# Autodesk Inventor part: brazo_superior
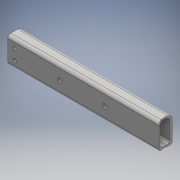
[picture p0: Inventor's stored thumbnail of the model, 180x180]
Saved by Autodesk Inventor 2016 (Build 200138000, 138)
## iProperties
Created: 2016-10
Part Number: brazo_superior
Material: Generic
Document SubType Name: Modeling
Designer: Ingenieria
Density: 1 g/cm^3
Appearance: Default
Mass: 948.547 g
Surface Area: 2981.55 cm^2
Volume: 948.547 cm^3
Author: Ingenieria
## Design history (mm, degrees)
sketch "Sketch1"
  geometry: C1 r 50.8 at (0, 0); C2 r 30.8 at (0, 0); 1 further point
  constraints: 2 centre point, 2 coincident
  dimensions: "d0" = 101.6 diameter of C1; "d1" = 61.6 diameter of C2
sketch "Sketch3"
  geometry: L1 (25, 38)-(25, -38); L2 (13, 50)-(-13, 50); L3 (-25, 38)-(-25, -38); L4 (-13, -50)-(13, -50); L5 (-19, -32)-(-19, 32); L6 (-7, 44)-(7, 44); L7 (19, 32)-(19, -32); L8 (7, -44)-(-7, -44); A1 r 12 centre (-7, 32) between (-7, 44) and (-19, 32); A2 r 12 centre (7, 32) between (19, 32) and (7, 44); A3 r 12 centre (-7, -32) between (-19, -32) and (-7, -44); A4 r 12 centre (7, -32) between (7, -44) and (19, -32); A5 r 12 centre (-13, 38) between (-13, 50) and (-25, 38); A6 r 12 centre (13, 38) between (25, 38) and (13, 50); A7 r 12 centre (13, -38) between (13, -50) and (25, -38); A8 r 12 centre (-13, -38) between (-25, -38) and (-13, -50); 5 further points
  constraints: 16 end point, 16 point on circle, 16 tangent, 8 centre point, 8 point on line, 4 perpendicular, 3 equal radius, 1 horizontal, 3 other
  dimensions: "d5" = 100 distance of point (25, 50) point (25, -50); "d6" = 50 distance of point (25, 50) point (-25, 50); "d7" = 100 distance of point (-25, 50) point (-25, -50); "d8" = 6 distance between parallel lines of L3 L5; "d9" = 12 radius of A1; "d10" = 12 radius of A5; "d11" = 12 radius of A6; "d12" = 12 radius of A7; "d13" = 12 radius of A8; "d14" = 25 distance from line of L1 point (0, 0); "d15" = 50 distance from line of point (0, 0) L4
extrude "Extrusion1" new body sketch "Sketch3" distance "d16" = 617; taper "d17" = 0 deg
extrude "Extrusion2" cut sketch "Sketch1" stored distance "d18" = 100; taper "d19" = 0 deg
sketch "Sketch4"
  geometry: L1 (567.892, -12)-(566.2, -12) reference; L2 (566.2, -6)-(566.685, -6) reference; L3 (0, 0)-(0, 76) reference; L4 (572.777, 0)-(572.777, 76) reference; L5 (566.2, -6)-(566.2, 175.196); L6 (0, 76)-(0, 0) reference; L7 (0, 38)-(566.2, 38); L8 (283.1, 38)-(283.1, 141.275); L9 (368.1, 38)-(368.1, 141.275); L10 (198.1, 38)-(198.1, 141.275); L11 (0, 58)-(574.2, 58); L12 (0, 18)-(574.2, 18); L13 (27, 0)-(27, 76); C1 r 8.5 at (198.1, 38); C2 r 8.5 at (368.1, 38); C3 r 6.5 at (27, 58); C4 r 6.5 at (27, 18); 1 further point
  constraints: 16 end point, 5 parallel, 5 point on line, 4 centre point, 2 coincident, 2 midpoint, 2 vertical, 1 perpendicular
  dimensions: "d22" = 85 distance between parallel lines of L8 L9; "d23" = 85 distance between parallel lines of L8 L10; "d24" = 17 diameter of C1; "d25" = 17 diameter of C2; "d26" = 20 distance between parallel lines of L7 L11; "d27" = 20 distance between parallel lines of L7 L12; "d28" = 27 distance between parallel lines of L3 L13; "d29" = 13 diameter of C3; "d30" = 13 diameter of C4; "d31" = 20 distance from line of L11 L10.start; "d32" = 170 distance of L9.start L10.start
extrude "Extrusion3" cut sketch "Sketch4" stored distance "d33" = 100; taper "d34" = 0 deg
body "Solid1"
other parameters: "sa_0" = 1e+10
